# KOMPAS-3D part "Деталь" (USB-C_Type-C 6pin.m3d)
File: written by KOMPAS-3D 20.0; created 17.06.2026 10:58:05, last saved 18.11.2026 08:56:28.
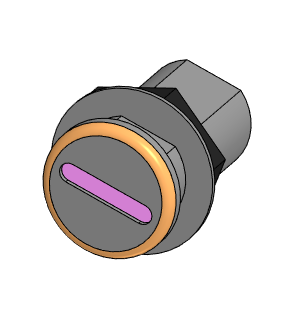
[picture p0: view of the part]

Document properties: Полное имя файла: D:\RicWork\Project-EPS32\box_compas\разъемы\USB-C_Type-C 6pin.m3d

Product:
- Part/product: Деталь
    Масса: 0.017827

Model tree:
1. Эскиз:1
2. Элемент выдавливания:1
     Расстояние 1 = 2
3. Эскиз:2  (with: Элемент выдавливания:1)
4. Элемент выдавливания:2
     Расстояние 1 = 19
5. Скругление:1  (with: Элемент выдавливания:1)
     Радиус = 1
6. Эскиз:4  (with: Элемент выдавливания:1, Скругление:1)
7. Элемент выдавливания:4
     Расстояние 2 = 1
8. Скругление:3  (with: Элемент выдавливания:4)
     Радиус = 1
9. Смещенная плоскость:1  (with: Элемент выдавливания:1)
     Расстояние = 4.5
10. Эскиз:5
11. Элемент выдавливания:5
     Расстояние 1 = 3
12. Эскиз:6
13. Элемент выдавливания:6  (with: Элемент выдавливания:4)
     Расстояние 1 = 0.5
14. Эскиз:7  (with: Элемент выдавливания:5)
15. Элемент выдавливания:7
     Расстояние 1 = 0.5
